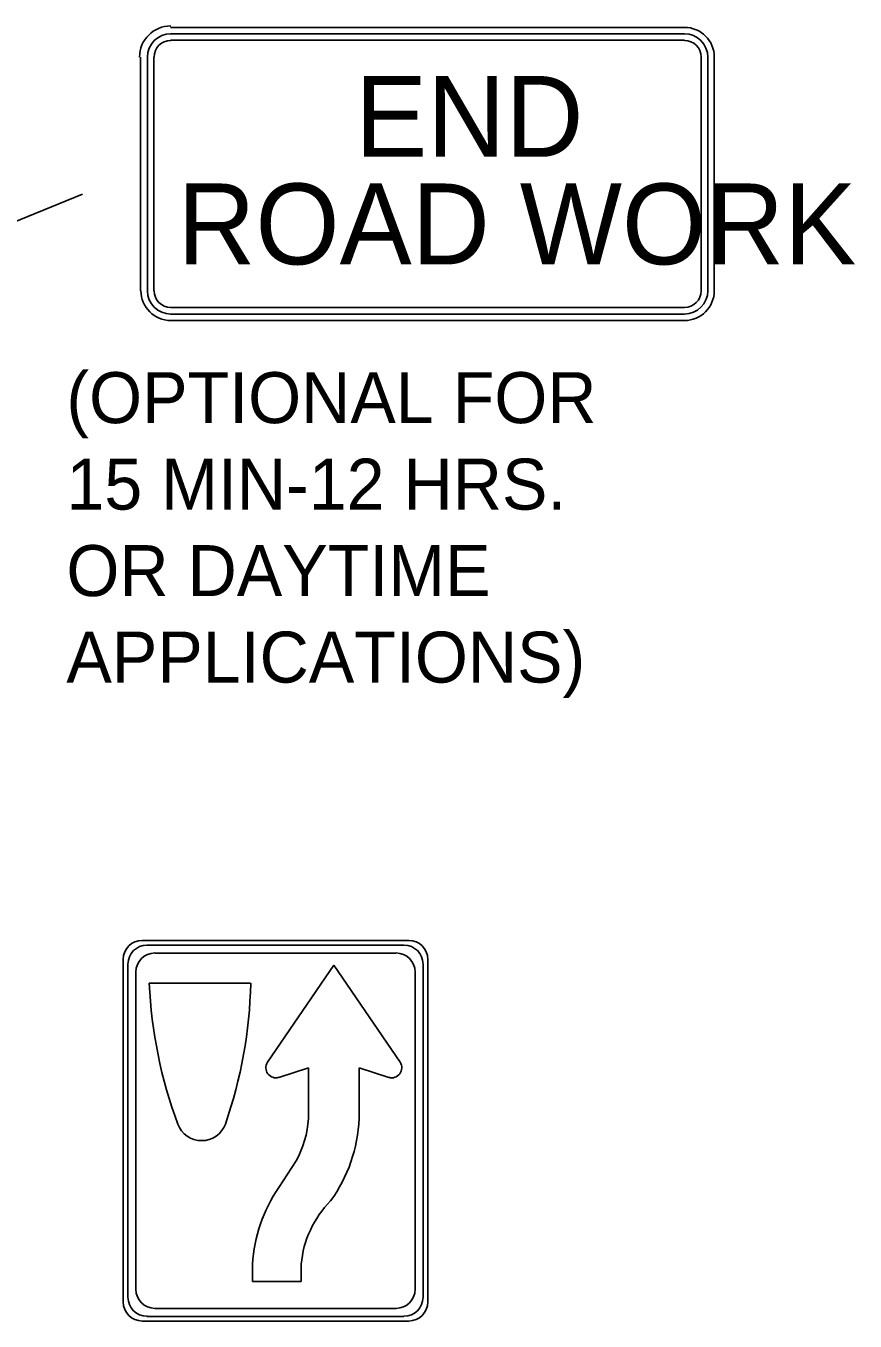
# Model space of a CAD drawing. Extents: x 1531.4 to 1538.6, y 1528.5 to 1539.8.
# Drawn here: x 1535.707 to 1536.683, y 1536.822 to 1538.346 of the extents above; entities that cross this region are included whole.
import ezdxf

# ---------------------------------------------------------------- set-up
doc = ezdxf.new("R2010")
doc.units = 0
for name, color, linetype in [('DETL-DIMS', 7, 'Continuous'), ('DETL-LINE', 7, 'Continuous'), ('DETL-NOTE', 7, 'Continuous')]:
    doc.layers.add(name, color=color, linetype=linetype)

msp = doc.modelspace()

# ---------------------------------------------------------------- linework, layer by layer
at = {"layer": 'DETL-DIMS'}
msp.add_line((1535.5194, 1538.0446), (1535.7735, 1538.1484), dxfattribs=at)
at = {"layer": 'DETL-LINE'}
for p, q in [((1535.8773, 1538.3446), (1536.4823, 1538.3446)), ((1535.8773, 1538.337), (1536.4823, 1538.337)), ((1535.8773, 1538.337), (1536.4823, 1538.337)), ((1535.8774, 1538.337), (1535.8773, 1538.337)), ((1536.4823, 1538.3296), (1535.8773, 1538.3296)), ((1535.8773, 1538.3296), (1536.4823, 1538.3296)), ((1535.8774, 1538.3293), (1535.8773, 1538.3296)), ((1535.8419, 1538.0347), (1535.8419, 1538.3097)), ((1535.85, 1538.0347), (1535.85, 1538.3097)), ((1535.85, 1538.0347), (1535.85, 1538.3097)), ((1535.8574, 1538.3097), (1535.8574, 1538.0347)), ((1535.8574, 1538.0347), (1535.8574, 1538.3097)), ((1536.5018, 1538.0347), (1536.5018, 1538.3097)), ((1536.5018, 1538.3097), (1536.5018, 1538.0347)), ((1536.5098, 1538.3097), (1536.5098, 1538.0347)), ((1536.5098, 1538.3097), (1536.5098, 1538.0347)), ((1536.5173, 1538.3097), (1536.5173, 1538.0347)), ((1535.8499, 1538.0347), (1535.85, 1538.0347)), ((1535.8773, 1538.0151), (1536.4823, 1538.0151)), ((1536.4823, 1538.0151), (1535.8773, 1538.0151)), ((1536.4823, 1538.0072), (1535.8773, 1538.0072)), ((1536.4823, 1538.0072), (1535.8773, 1538.0072)), ((1536.4823, 1537.9995), (1535.8773, 1537.9995)), ((1535.8439, 1537.27), (1536.1576, 1537.27)), ((1536.1519, 1537.2645), (1535.8494, 1537.2645)), ((1535.8215, 1536.8443), (1535.8215, 1537.2476)), ((1535.8588, 1537.255), (1536.1426, 1537.255)), ((1535.8588, 1537.255), (1535.8588, 1537.255)), ((1536.1801, 1537.2476), (1536.1801, 1536.8443)), ((1535.827, 1537.2421), (1535.827, 1536.8497)), ((1535.8365, 1536.8591), (1535.8365, 1537.2327)), ((1535.9915, 1537.1265), (1536.0695, 1537.2409)), ((1536.0695, 1537.2409), (1536.1475, 1537.1265)), ((1536.1651, 1537.2327), (1536.1651, 1536.8591)), ((1536.1744, 1536.8497), (1536.1744, 1537.2421)), ((1535.9715, 1537.2195), (1535.852, 1537.2195)), ((1536.0396, 1537.1199), (1536.0047, 1537.1087)), ((1536.0396, 1537.0602), (1536.0396, 1537.1199)), ((1536.134, 1537.1087), (1536.0991, 1537.1199)), ((1536.0993, 1537.1199), (1536.0993, 1537.0602)), ((1536.0047, 1536.9791), (1536.025, 1537.0106)), ((1535.9735, 1536.8683), (1535.9735, 1536.8886)), ((1536.0309, 1536.8886), (1536.0309, 1536.8683)), ((1536.0309, 1536.8683), (1535.9735, 1536.8683)), ((1536.1426, 1536.8368), (1535.8588, 1536.8368)), ((1536.1576, 1536.8218), (1535.8439, 1536.8218)), ((1535.8494, 1536.8273), (1536.1519, 1536.8273))]:
    msp.add_line(p, q, dxfattribs=at)
for centre, radius, start, end in [((1535.8775, 1538.3096), 0.0368, 90, 180), ((1536.4822, 1538.3096), 0.0351, 0, 90), ((1535.8775, 1538.3096), 0.0275, 90, 180), ((1535.8775, 1538.3096), 0.0275, 90, 180), ((1535.8775, 1538.3096), 0.0197, 90, 180), ((1535.8775, 1538.3096), 0.0197, 90, 180), ((1536.4822, 1538.3096), 0.0275, 0, 90), ((1536.4822, 1538.3096), 0.0275, 0, 90), ((1536.4822, 1538.3096), 0.0197, 0, 90), ((1536.4822, 1538.3096), 0.0197, 0, 90), ((1535.8775, 1538.0347), 0.0351, 180, 270), ((1535.8775, 1538.0347), 0.0275, 180, 270), ((1535.8775, 1538.0347), 0.0275, 180, 270), ((1535.8775, 1538.0347), 0.0197, 180, 270), ((1535.8775, 1538.0347), 0.0197, 180, 270), ((1536.4822, 1538.0347), 0.0197, 270, 0), ((1536.4822, 1538.0347), 0.0275, 270, 0), ((1536.4822, 1538.0347), 0.0351, 270, 0), ((1536.4822, 1538.0347), 0.0275, 270, 0), ((1536.4822, 1538.0347), 0.0197, 270, 0), ((1535.8439, 1537.2476), 0.0224, 90, 180), ((1535.8495, 1537.242), 0.0224, 90, 180), ((1536.152, 1537.242), 0.0224, 0, 90), ((1536.1576, 1537.2476), 0.0224, 0, 90), ((1535.8588, 1537.2327), 0.0224, 90, 180), ((1536.1427, 1537.2327), 0.0224, 0, 90), ((1536.398, 1537.2438), 0.5464, 182.5529, 200.3658), ((1535.4244, 1537.2325), 0.5474, 340.9328, 358.6381), ((1536.0011, 1537.1199), 0.0117, 145.7397, 288), ((1536.1377, 1537.1199), 0.0117, 252, 34.2603), ((1535.9138, 1537.0641), 0.0299, 200.3641, 339.6359), ((1535.9203, 1537.0681), 0.1196, 331.1838, 356.1678), ((1535.9203, 1537.0681), 0.1792, 324.1907, 357.4446), ((1536.151, 1536.8783), 0.1777, 145.3872, 176.6343), ((1536.151, 1536.8783), 0.1204, 135.1307, 175.032), ((1535.8588, 1536.8592), 0.0224, 180, 270), ((1536.1427, 1536.8592), 0.0224, 270, 360), ((1535.8439, 1536.8443), 0.0224, 180, 270), ((1535.8495, 1536.8499), 0.0224, 180, 270), ((1536.152, 1536.8499), 0.0224, 270, 360), ((1536.1576, 1536.8443), 0.0224, 270, 360)]:
    msp.add_arc(centre, radius, start, end, dxfattribs=at)

# ---------------------------------------------------------------- texts
for s, p in [('END', (1536.0945, 1538.1923)), ('ROAD WORK', (1535.8852, 1538.0657))]:
    msp.add_text(s, height=0.09521, rotation=360, dxfattribs=at).set_placement(p)
at = {"layer": 'DETL-NOTE'}
for s, p in [('(OPTIONAL FOR', (1535.7546, 1537.8788)), ('15 MIN-12 HRS. ', (1535.7546, 1537.777)), ('OR DAYTIME', (1535.7546, 1537.6752)), ('APPLICATIONS)', (1535.7546, 1537.5734))]:
    msp.add_text(s, height=0.06, dxfattribs=at).set_placement(p)

doc.saveas('drawing.dxf')
